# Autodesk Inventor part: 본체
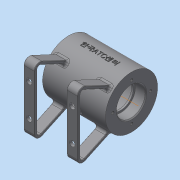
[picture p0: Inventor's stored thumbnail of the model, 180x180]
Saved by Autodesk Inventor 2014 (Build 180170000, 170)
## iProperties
Created: 2021-12
Part Number: 본체
Material: 일반
Document SubType Name: Modeling
Designer: dg
Density: 1 g/cm^3
Appearance: 기본값
Author: dg
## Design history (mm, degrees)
sketch "스케치1"
  geometry: L1 (0, 0)-(70, 0); L2 (0, 16)-(0, 29); L3 (0, 16)-(12, 16); L4 (12, 16)-(12, 14); L5 (12, 14)-(14, 14); L6 (14, 14)-(14, 21); L7 (14, 21)-(56, 21); L8 (56, 21)-(56, 14); L9 (56, 14)-(58, 14); L10 (58, 14)-(58, 16); L11 (58, 16)-(70, 16); L12 (70, 16)-(70, 29); L13 (0, 29)-(70, 29)
  constraints: 26 end point, 6 perpendicular, 5 parallel, 1 horizontal, 1 vertical alignment
  dimensions: "d0" = 70 distance of L1.start L1.end; "d1" = 32 diameter of L2.start L1; "d2" = 12 distance of L2.start L3.end; "d3" = 2 distance of L3.end L4.end; "d4" = 2 distance of L4.end L5.end; "d5" = 42 diameter of L6.end L1; "d6" = 42 distance of L6.end L7.end; "d7" = 2 distance of L8.end L9.end; "d8" = 2 distance of L9.end L10.end; "d9" = 12 distance of L10.end L11.end; "d10" = 32 diameter of L11 L1; "d11" = 58 diameter of L12.end L1; "d12" = 58 diameter of L2.end L1
revolve "회전1" sketch "스케치1" stored, may be unused: angle "d13" = 90 deg
node "작업축1"
fillet "모깎기1" dims "d14" = 3
fillet "모깎기2" dims "d15" = 0.3
node "작업 평면1"
sketch "스케치2"
  geometry: L1 (-55, 40)-(-55, -40); L2 (-55, 40)-(-17.993, 22.743); L3 (-55, -40)-(-17.993, -22.743); L4 (-20.438, -20.574)-(-52, -35.291); L5 (-52, -35.291)-(-52, 35.291); L6 (-52, 35.291)-(-20.438, 20.574); A1 r 29 centre (0, 0) between (-17.993, 22.743) and (-20.438, 20.574) reference; 1 further point
  constraints: 12 end point, 4 point on circle, 2 parallel, 1 vertical
  dimensions: "d17" = 55 distance from line of L1 point (0, 0); "d18" = 80 distance of L1.start L1.end; "d19" = 40 vertical distance of L1.start point (0, 0); "d20" = 65 deg angle of L1 L2; "d21" = 65 deg angle of L1 L3; "d22" = 3 distance between parallel lines of L3 L4; "d69" = 3 distance between parallel lines of L2 L6; "d70" = 3 distance between parallel lines of L5 L1
extrude "돌출1" join sketch "스케치2" stored distance "d25" = 60; taper "d26" = 0 deg
sketch "스케치4"
  geometry: C1 r 16 at (0, 0) reference; C2 r 29 at (0, 0) reference; A1 r 21 centre (0, 0) between (0, 21) and (21, 0); 2 further points
  constraints: 4 point on circle, 2 horizontal alignment, 2 vertical alignment, 1 centre point, 1 coincident
  dimensions: "d38" = 42 diameter of A1
hole "구멍1" sketch "스케치4" at (0, 21), (21, 0), (0, -21), (-21, 0) diameter "d39" = 3.242; stored, may be unused: countersink angle "d43" = 90 deg, drill point angle "d45" = 118 deg; dims "d40" = 8, "d41" = 4, "d42" = 2, "d44" = 10
node "작업 평면2"
sketch "스케치5"
  geometry: L1 (0, 29)-(0, -29) reference; C1 r 5 at (-35, 0); 2 further points
  constraints: 1 centre point, 1 horizontal alignment, 1 midpoint
  dimensions: "d47" = 35 distance from line of L1 C1.centre; "d48" = 10 diameter of C1
extrude "돌출4" join sketch "스케치5" stored distance "d49" = 36; taper "d50" = 0 deg
sketch "스케치6"
  geometry: C1 r 5 at (0, 0) reference; 2 further points
  constraints: 1 coincident
hole "구멍2" sketch "스케치6" at (0, 0) diameter "d51" = 5.188; stored, may be unused: countersink angle "d55" = 90 deg, drill point angle "d57" = 118 deg; dims "d52" = 6, "d53" = 4, "d54" = 2, "d56" = 8
fillet "모깎기6" dims "d58" = 1
chamfer "모따기1" distance "d59" = 1; stored, may be unused: second distance "d60" = 2, angle "d61" = 45 deg
sketch "스케치7"
  geometry: C1 r 5 at (0, 0) reference; C2 r 1.5 at (0, 0); 1 further point
  constraints: 1 centre point, 1 coincident
  dimensions: "d62" = 3 diameter of C2
extrude "돌출5" cut sketch "스케치7" stored distance "d63" = 36; taper "d64" = 0 deg
extrude "돌출6" cut sketch "스케치2" stored distance "d71" = 36; taper "d72" = 0 deg
fillet "모깎기8" dims "d73" = 6
fillet "모깎기9" dims "d74" = 3
sketch "스케치10"
  geometry: L1 (60, 6)-(60, 0) reference; L2 (-5, -30.582)-(-8.484, -30.582); L3 (0, 0)-(12, 0) reference; L4 (60, 0)-(48, 0) reference; C1 r 3 at (6, -12.582); C2 r 3 at (54, -12.582); C3 r 3 at (6, -48.582); C4 r 3 at (54, -48.582); 3 further points
  constraints: 4 centre point, 2 end point, 2 midpoint, 2 symmetric about line, 2 vertical alignment, 1 horizontal alignment, 1 perpendicular, 2 other
  dimensions: "d75" = 18 vertical distance of L2.start C1.centre; "d77" = 6 diameter of C1; "d79" = 6 diameter of C2
extrude "돌출7" cut sketch "스케치10" distance "d80" = 36; taper "d81" = 0 deg
fillet "모깎기10" dims "d82" = 0.5
fillet "모깎기11" dims "d83" = 3
node "작업 평면3"
sketch "스케치11"
  geometry: L1 (70, -29)-(70, 29) reference; L2 (0, -29)-(70, -29) reference; L3 (0, -29)-(0, 29) reference; 3 further points
  constraints: 1 horizontal alignment, 1 midpoint, 1 vertical alignment, 1 other
  dimensions: "d88" = 29 vertical distance of point (35, 0) L3.end (derived); "d89" = 35 distance from line of point (35, 0) L3 (derived)
feature "엠보싱1" sketch "스케치11" dims "d0" = 70, "d1" = 32, "d2" = 12, "d3" = 2, "d4" = 2, "d5" = 42, "d6" = 42, "d7" = 2, "d8" = 2, "d9" = 12, "d10" = 32, "d11" = 58, "d12" = 58, "d86" = 0.5, "d87" = 0
sketch "스케치12"
  geometry: L1 (0, 0)-(-30.07, -10.945); L2 (0, 0)-(-2.767, 0); L3 (-30.07, -10.945)-(-32.122, -5.306); L4 (-32.122, -5.306)-(-24.74, -2.619); L5 (-24.74, -2.619)-(-22.687, -8.258)
  constraints: 10 end point, 3 perpendicular, 1 horizontal, 1 point on line
  dimensions: "d90" = 32 distance of L1.start L1.end; "d91" = 20 deg angle of L1 L2; "d92" = 6 distance of L1.end L3.end
revolve "회전2" sketch "스케치12" stored, may be unused: angle "d93" = 90 deg
sketch "스케치13"
  geometry: C1 r 6 at (0, 0) reference; 2 further points
  constraints: 1 coincident
hole "구멍3" sketch "스케치13" at (0, 0) diameter "d94" = 5.188; stored, may be unused: countersink angle "d98" = 90 deg, drill point angle "d100" = 118 deg; dims "d95" = 13, "d96" = 4, "d97" = 2, "d99" = 15
fillet "모깎기12" dims "d101" = 1
node "솔리드1"
mirror "대칭1"
other parameters: "d16" = 35, "d23" = 24.474, "d46" = 32, "d84" = 29.5
